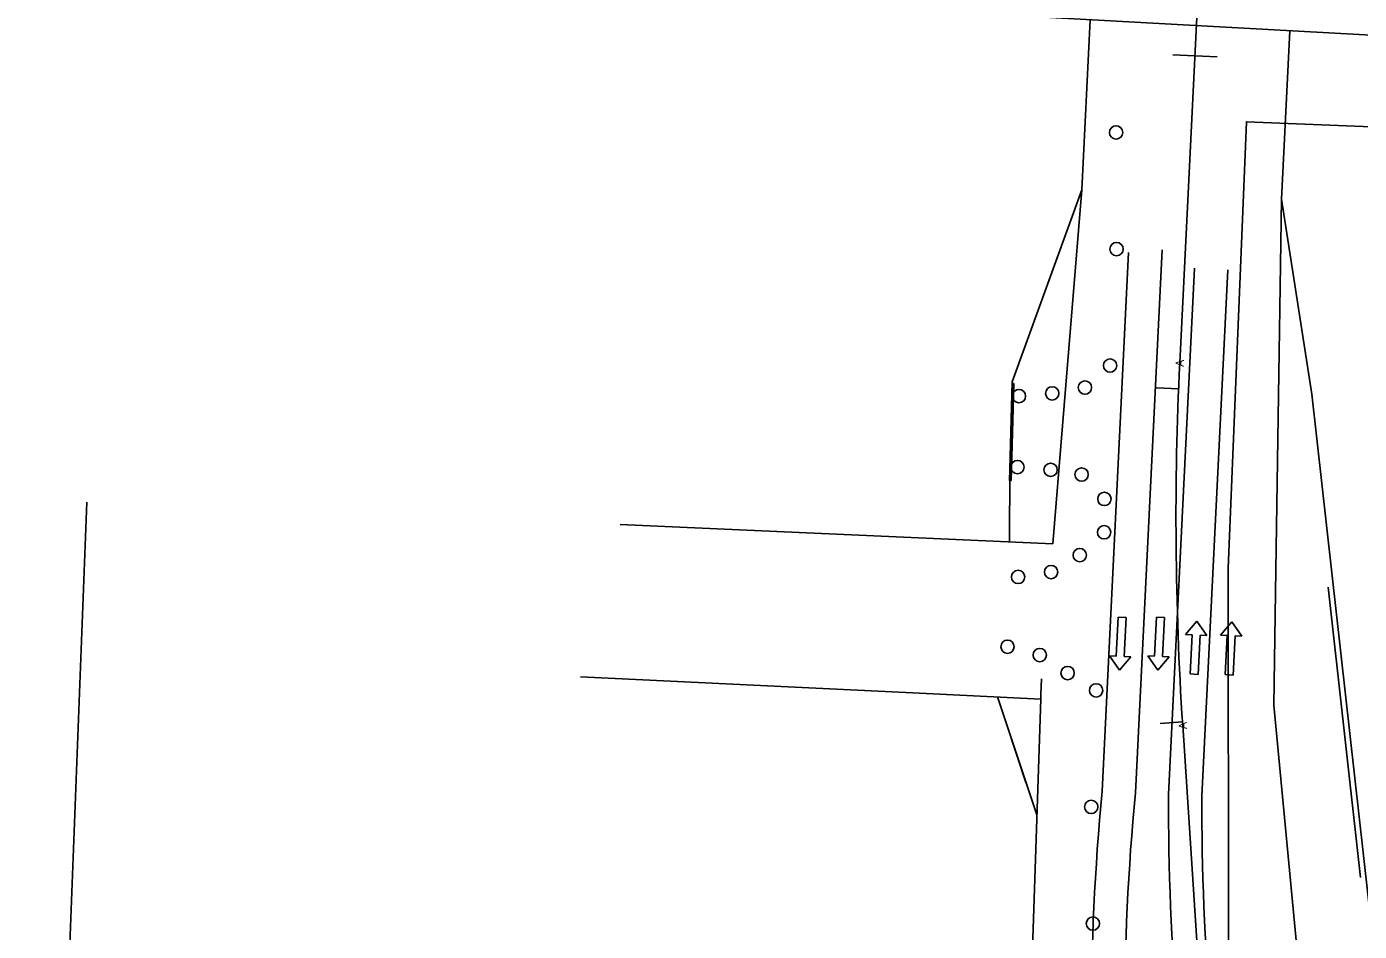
# Model space of a CAD drawing. Extents: x 679444 to 687671, y 733868 to 736107.
# Drawn here: x 685888.8 to 686288.6, y 735087.7 to 735359.1 of the extents above; entities that cross this region are included whole.
import ezdxf

# ---------------------------------------------------------------- set-up
doc = ezdxf.new("R2010")
doc.units = 0
for name, color, linetype in [('border All Plan 20-40 - Level 1', 7, 'Continuous'), ('Clipping Boundary', 7, 'Continuous'), ('MOT Stage 1', 7, 'Continuous'), ('MOT Stage 1 Lanes', 7, 'Continuous'), ('R_Horz Alg', 7, 'Continuous'), ('R_Horz Alg Station', 7, 'Continuous'), ('R_TYPE_A_CURB', 7, 'Continuous'), ('RW-EX', 7, 'Continuous'), ('RW-PR', 7, 'Continuous')]:
    doc.layers.add(name, color=color, linetype=linetype)

# ---------------------------------------------------------------- blocks, each defined once
blk = doc.blocks.new('BAREL_1801')
at = {"layer": 'MOT Stage 1'}
blk.add_circle((0, 0.01), 2.88, dxfattribs=at)
blk = doc.blocks.new('BAREL_1802')
at = {"layer": 'MOT Stage 1'}
blk.add_circle((0, 0.01), 2.88, dxfattribs=at)
blk = doc.blocks.new('BAREL_1803')
at = {"layer": 'MOT Stage 1'}
blk.add_circle((0, 0.01), 2.88, dxfattribs=at)
blk = doc.blocks.new('BAREL_1804')
at = {"layer": 'MOT Stage 1'}
blk.add_circle((0, 0.01), 2.88, dxfattribs=at)
blk = doc.blocks.new('BAREL_1805')
at = {"layer": 'MOT Stage 1'}
blk.add_circle((0, 0.01), 2.88, dxfattribs=at)
blk = doc.blocks.new('BAREL_1806')
at = {"layer": 'MOT Stage 1'}
blk.add_circle((0, 0.01), 2.88, dxfattribs=at)
blk = doc.blocks.new('BAREL_1841')
at = {"layer": 'MOT Stage 1'}
blk.add_circle((0, 0.01), 2.88, dxfattribs=at)
blk = doc.blocks.new('BAREL_1842')
at = {"layer": 'MOT Stage 1'}
blk.add_circle((0, 0.01), 2.88, dxfattribs=at)
blk = doc.blocks.new('BAREL_1843')
at = {"layer": 'MOT Stage 1'}
blk.add_circle((0, 0.01), 2.88, dxfattribs=at)
blk = doc.blocks.new('BAREL_1844')
at = {"layer": 'MOT Stage 1'}
blk.add_circle((0, 0.01), 2.88, dxfattribs=at)
blk = doc.blocks.new('BAREL_1845')
at = {"layer": 'MOT Stage 1'}
blk.add_circle((0, 0.01), 2.88, dxfattribs=at)
blk = doc.blocks.new('BAREL_1846')
at = {"layer": 'MOT Stage 1'}
blk.add_circle((0, 0.01), 2.88, dxfattribs=at)
blk = doc.blocks.new('BAREL_1847')
at = {"layer": 'MOT Stage 1'}
blk.add_circle((0, 0.01), 2.88, dxfattribs=at)
blk = doc.blocks.new('BAREL_1848')
at = {"layer": 'MOT Stage 1'}
blk.add_circle((0, 0.01), 2.88, dxfattribs=at)
blk = doc.blocks.new('BAREL_1849')
at = {"layer": 'MOT Stage 1'}
blk.add_circle((0, 0.01), 2.88, dxfattribs=at)
blk = doc.blocks.new('BAREL_1850')
at = {"layer": 'MOT Stage 1'}
blk.add_circle((0, 0.01), 2.88, dxfattribs=at)
blk = doc.blocks.new('BAREL_1851')
at = {"layer": 'MOT Stage 1'}
blk.add_circle((0, 0.01), 2.88, dxfattribs=at)
blk = doc.blocks.new('BAREL_1852')
at = {"layer": 'MOT Stage 1'}
blk.add_circle((0, 0.01), 2.88, dxfattribs=at)
blk = doc.blocks.new('SARROW_225')
at = {"layer": 'MOT Stage 1'}
for p, q in [((-6, -29.42), (-6, 0)), ((0, 0), (-6, 0)), ((0, -29.42), (0, 0)), ((-6, -29.42), (-11, -29.42)), ((-3, -39.81), (-11, -29.42)), ((5, -29.42), (-3, -39.81)), ((5, -29.42), (0, -29.42))]:
    blk.add_line(p, q, dxfattribs=at)
blk = doc.blocks.new('SARROW_226')
at = {"layer": 'MOT Stage 1'}
for p, q in [((-6, -29.42), (-6, 0)), ((0, 0), (-6, 0)), ((0, -29.42), (0, 0)), ((-6, -29.42), (-11, -29.42)), ((-3, -39.81), (-11, -29.42)), ((5, -29.42), (-3, -39.81)), ((5, -29.42), (0, -29.42))]:
    blk.add_line(p, q, dxfattribs=at)
blk = doc.blocks.new('SARROW_227')
at = {"layer": 'MOT Stage 1'}
for p, q in [((-6, -29.42), (-6, 0)), ((0, 0), (-6, 0)), ((0, -29.42), (0, 0)), ((-6, -29.42), (-11, -29.42)), ((-3, -39.81), (-11, -29.42)), ((5, -29.42), (-3, -39.81)), ((5, -29.42), (0, -29.42))]:
    blk.add_line(p, q, dxfattribs=at)
blk = doc.blocks.new('BAREL_1870')
at = {"layer": 'MOT Stage 1'}
blk.add_circle((0, 0.01), 2.88, dxfattribs=at)
blk = doc.blocks.new('BAREL_1871')
at = {"layer": 'MOT Stage 1'}
blk.add_circle((0, 0.01), 2.88, dxfattribs=at)
blk = doc.blocks.new('SARROW_228')
at = {"layer": 'MOT Stage 1'}
for p, q in [((-6, -29.42), (-6, 0)), ((0, 0), (-6, 0)), ((0, -29.42), (0, 0)), ((-6, -29.42), (-11, -29.42)), ((-3, -39.81), (-11, -29.42)), ((5, -29.42), (-3, -39.81)), ((5, -29.42), (0, -29.42))]:
    blk.add_line(p, q, dxfattribs=at)

msp = doc.modelspace()

# ---------------------------------------------------------------- linework, layer by layer
at = {"layer": 'border All Plan 20-40 - Level 1'}
msp.add_line((685446.82, 735403.36), (687025.3, 735315.9), dxfattribs=at)
at = {"layer": 'Clipping Boundary'}
msp.add_lwpolyline([(686301.74, 734922.73), (686278.61, 734914.83), (686249.36, 735085.15), (686249.3, 735196.57), (686254.77, 735330.58), (686292.31, 735329.05), (686322.77, 734958.42)], close=True, dxfattribs=at)
at = {"layer": 'MOT Stage 1 Lanes'}
for points in [[(686221.44, 735129.26), (686229.44, 735292.13)], [(686211.45, 735129.75), (686219.39, 735291.41)], [(686231.42, 735128.77), (686239.18, 735286.65)], [(686241.41, 735128.27), (686249.17, 735286.16)]]:
    msp.add_lwpolyline(points, dxfattribs=at)
for centre, radius, start, end in [((686946.79, 735060.88), 738.56, 174.64944, 185.44699), ((686946.77, 735060.88), 728.55, 174.61469, 185.41281), ((686944.02, 735124.57), 712.61, 179.66251, 190.45935), ((686944, 735124.56), 702.6, 179.69727, 190.49468)]:
    msp.add_arc(centre, radius, start, end, dxfattribs=at)
at = {"layer": 'R_Horz Alg'}
for p, q in [((686234.78, 735258.3), (686249.07, 735549.04)), ((686255.4, 734845.31), (686235.64, 735149.56))]:
    msp.add_line(p, q, dxfattribs=at)
msp.add_arc((687188.56, 735211.44), 954.93, 177.18772, 183.71573, dxfattribs=at)
at = {"layer": 'R_Horz Alg Station'}
for points in [[(686232.65, 735350.71), (686245.97, 735350.05)], [(686227.77, 735250.77), (686234.43, 735250.5)], [(686228.92, 735150.13), (686235.58, 735150.55)]]:
    msp.add_lwpolyline(points, dxfattribs=at)
at = {"layer": 'R_TYPE_A_CURB'}
for p, q in [((686184.46, 735252.11), (686184.96, 735252.1)), ((686183.73, 735223.02), (686184.23, 735223.01))]:
    msp.add_line(p, q, dxfattribs=at)
for points in [[(686183.73, 735223.02), (686183.74, 735226.25), (686184.46, 735252.11)], [(686184.23, 735223.01), (686184.24, 735226.24), (686184.96, 735252.1)], [(686289.03, 735103.92), (686279.27, 735191.01)], [(686188.63, 735132.43), (686182.76, 735149.94)]]:
    msp.add_lwpolyline(points, dxfattribs=at)
at = {"layer": 'RW-EX'}
for p, q in [((685894.65, 734899.71), (685906.88, 735216.51)), ((686066.93, 735209.73), (686196.68, 735203.99)), ((686282.11, 734952.68), (686263.01, 735155.56))]:
    msp.add_line(p, q, dxfattribs=at)
for points in [[(686196.68, 735203.99), (686205.39, 735310.21), (686207.85, 735361.16)], [(686263.01, 735155.56), (686263.62, 735196.09), (686265.32, 735307.32), (686267.76, 735357.83)], [(686193.04, 735157.41), (686154.73, 735159.27), (686054.94, 735164.12)], [(686189.41, 735046.56), (686193.04, 735157.41), (686193.09, 735158.93), (686193.31, 735163.53)]]:
    msp.add_lwpolyline(points, dxfattribs=at)
at = {"layer": 'RW-PR'}
msp.add_line((686180.05, 735158.04), (686191.9, 735122.66), dxfattribs=at)
for points in [[(686205.39, 735310.21), (686184.48, 735252.55), (686183.74, 735226.25), (686183.66, 735204.57)], [(686265.32, 735307.32), (686274.4, 735248.86), (686280.38, 735195.3), (686292.55, 735086.37), (686296.14, 735054.27), (686310.81, 734922.92), (686343.56, 734897.83)]]:
    msp.add_lwpolyline(points, dxfattribs=at)

# ---------------------------------------------------------------- block references
at = {"layer": 'MOT Stage 1'}
for name, p, xscale, yscale, rotation in [('BAREL_1871', (686215.66, 735327.39), 0.6945420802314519, 0.6945420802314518, 87.04179557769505), ('BAREL_1870', (686215.8, 735292.39), 0.6945420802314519, 0.6945420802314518, 87.04179557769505), ('BAREL_1852', (686213.86, 735257.45), 0.6945420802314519, 0.6945420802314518, 87.04179557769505), ('BAREL_1851', (686206.34, 735250.85), 0.6945420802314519, 0.6945420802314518, 87.04179557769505), ('BAREL_1803', (686186.53, 735248.3), 0.6945420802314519, 0.6945420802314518, 87.04179557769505), ('BAREL_1850', (686196.5, 735249.11), 0.6945420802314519, 0.6945420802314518, 87.04179557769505), ('BAREL_1804', (686186.07, 735226.99), 0.6945420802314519, 0.6945420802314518, 87.04179557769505), ('BAREL_1805', (686196.03, 735226.18), 0.6945420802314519, 0.6945420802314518, 87.04179557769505), ('BAREL_1806', (686205.33, 735224.75), 0.6945420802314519, 0.6945420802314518, 87.04179557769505), ('BAREL_1845', (686212.15, 735217.43), 0.6945420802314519, 0.6945420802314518, 87.04179557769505), ('BAREL_1846', (686212.07, 735207.43), 0.6945420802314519, 0.6945420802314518, 87.04179557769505), ('BAREL_1847', (686204.78, 735200.59), 0.6945420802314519, 0.6945420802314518, 87.04179557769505), ('BAREL_1849', (686186.27, 735194.04), 0.6945420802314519, 0.6945420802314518, 87.04179557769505), ('BAREL_1848', (686196.16, 735195.52), 0.6945420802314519, 0.6945420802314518, 87.04179557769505), ('SARROW_225', (686218.68, 735181.91), 0.4000000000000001, 0.4000000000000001, -2.7722917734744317), ('SARROW_228', (686230.18, 735181.91), 0.4000000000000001, 0.4000000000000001, -2.7722917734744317), ('SARROW_226', (686240.32, 735164.82), 0.39999999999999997, -0.4, -2.7722917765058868), ('SARROW_227', (686250.79, 735164.63), 0.39999999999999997, -0.4, -2.7722917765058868), ('BAREL_1802', (686183.09, 735173.12), 0.6945420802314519, 0.6945420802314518, 87.04179557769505), ('BAREL_1801', (686192.77, 735170.62), 0.6945420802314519, 0.6945420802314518, 87.04179557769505), ('BAREL_1844', (686201.13, 735165.23), 0.6945420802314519, 0.6945420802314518, 87.04179557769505), ('BAREL_1843', (686209.67, 735160.03), 0.6945420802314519, 0.6945420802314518, 87.04179557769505), ('BAREL_1842', (686208.22, 735125.06), 0.6945420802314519, 0.6945420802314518, 87.04179557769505), ('BAREL_1841', (686208.72, 735090.06), 0.6945420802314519, 0.6945420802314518, 87.04179557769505)]:
    msp.add_blockref(name, p, dxfattribs=dict(at, xscale=xscale, yscale=yscale, rotation=rotation))

# ---------------------------------------------------------------- texts
at = {"layer": 'R_Horz Alg'}
for rotation, p in [(87.1877, (686235.92, 735257.04)), (93.7157, (686236.92, 735148.44))]:
    msp.add_text('A', height=2.4, rotation=rotation, dxfattribs=at).set_placement(p)

doc.saveas('drawing.dxf')
